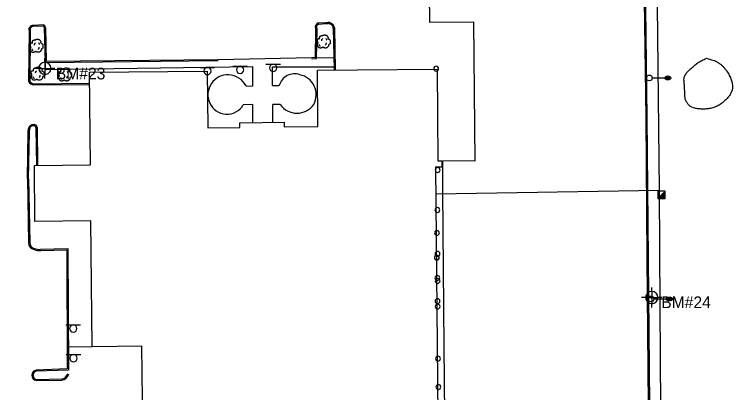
# Model space of a CAD drawing. Extents: x 2145380 to 2156929, y 139568 to 149130.
# Drawn here: x 2149393.4 to 2149761.7, y 142594.4 to 142788.2 of the extents above; entities that cross this region are included whole.
import ezdxf

# ---------------------------------------------------------------- set-up
doc = ezdxf.new("R2010")
doc.units = 0
for name, color, linetype in [('SURV_Benchmark', 7, 'Continuous'), ('SURV_Text', 7, 'Continuous'), ('TOPO_Asphalt', 7, 'Continuous'), ('TOPO_Building', 7, 'Continuous'), ('TOPO_Curb Back', 7, 'Continuous'), ('TOPO_Fence', 7, 'Continuous'), ('TOPO_Guardrail', 7, 'Continuous'), ('TOPO_Light Pole', 7, 'Continuous'), ('TOPO_Misc', 7, 'Continuous'), ('TOPO_Sidewalk', 7, 'Continuous'), ('TOPO_Sign', 7, 'Continuous'), ('TOPO_Tree', 7, 'Continuous'), ('TOPO_Tree Line', 7, 'Continuous')]:
    doc.layers.add(name, color=color, linetype=linetype)

# ---------------------------------------------------------------- blocks, each defined once
blk = doc.blocks.new('POST')
at = {"layer": 'TOPO_Misc'}
for start, end in [(89.99996, 180.00004), (179.99996, 270.00004), (359.99996, 90.00004), (269.99996, 0.00004)]:
    blk.add_arc((-0.01, 0.03), 3.16, start, end, dxfattribs=at)
blk = doc.blocks.new('LP')
at = {"layer": 'TOPO_Light Pole'}
blk.add_line((3.81, 0), (20.32, 0), dxfattribs=at)
for points in [[(20.32, 0), (27.94, 0)], [(20.32, 0), (23.5, 0)], [(20.83, 1.27), (27.43, 1.27)], [(20.83, 1.27), (23.5, 1.27)], [(23.71, 1.27), (27.43, 1.27)], [(23.71, 0), (27.94, 0)], [(20.83, -1.27), (27.43, -1.27)], [(20.83, -1.27), (23.5, -1.27)], [(23.71, -1.27), (27.43, -1.27)]]:
    blk.add_lwpolyline(points, dxfattribs=at)
blk.add_circle((0, 0), 3.81, dxfattribs=at)
blk.add_ellipse((24.13, 0), major_axis=(3.81, 0), ratio=0.666667, dxfattribs=at)
blk = doc.blocks.new('TREE')
at = {"layer": 'TOPO_Tree'}
for points in [[(-3.5, 17.6), (-3.1, 18.3), (-2.6, 18.8), (-1.9, 19.2), (-1, 19.7), (-0.2, 20), (0.7, 20.2), (1.6, 20.5), (2.5, 20.8), (3.4, 20.8), (4.1, 20.7), (4.8, 20.5), (5.5, 20.2), (6.4, 19.9), (7.3, 19.7), (8.2, 19.2), (9.4, 18.4), (10, 17.2), (10.8, 16), (11.2, 15.3), (11.6, 14.6), (11.9, 13.9), (12.2, 13.1), (11.4, 12), (11.9, 11.2), (12, 11), (12.2, 10.9), (12.4, 10.7), (12.9, 10.4), (13.5, 10), (14, 9.7), (14.7, 9.2), (15.4, 8.7), (16.1, 8.1), (16.7, 7.5), (16.9, 6.7), (17.1, 6), (17.6, 4.4), (17.7, 2.8), (17.7, 1.2), (17.7, -0.2), (17.8, -2.2), (16.6, -3), (15.5, -3.8), (14.3, -4.6), (13.2, -5.3)], [(-14.1, -0.4), (-14.2, 0.5), (-14.4, 1.4), (-14.6, 2.3), (-14.8, 3.2), (-15.5, 4), (-15.7, 4.9), (-15.8, 5.6), (-15.7, 6.3), (-15.7, 7), (-15.6, 7.9), (-15.7, 8.8), (-15.1, 9.7), (-14.6, 10.4), (-13.8, 10.5), (-13, 10.7), (-12.2, 11), (-11.1, 10), (-10.4, 10.7), (-9.4, 11.7), (-10.3, 13.3), (-9.8, 14.4), (-9.6, 15.1), (-9.3, 15.9), (-8.8, 16.5), (-8.2, 17.3), (-7.5, 17.7), (-6.7, 18.1), (-6.1, 18.4), (-5.6, 18.6), (-5.1, 18.7), (-4.5, 18.7), (-4, 18.5), (-3.5, 18.1)], [(13.2, -5.3), (13.3, -5.8), (13.4, -6.3), (13.4, -6.7), (13.8, -8.5), (12.2, -10), (10.8, -11.5), (10, -12.3), (9.1, -12.8), (8.2, -13.1), (6, -13.8), (3.3, -13.6), (1.3, -13.1), (0.5, -12.9), (-0.1, -11.4), (-0.8, -11.5), (-2, -11.6), (-3.3, -12.8), (-4.5, -13.1), (-6.1, -13.5), (-7.8, -14), (-9.3, -13.6), (-11.4, -13.1), (-12.8, -11.4), (-14.1, -9.4), (-15.3, -7.3), (-15.6, -5.1), (-15.1, -3), (-14.9, -1.9), (-13.9, -0.8), (-13.5, 0.1)], [(-4.2, 5.1), (-4.5, 6.1), (-4.3, 7.2), (-3.8, 8.2), (-3.3, 9.3), (-2.7, 10.3), (-1.6, 11)], [(5.9, 11.2), (6.5, 10.7), (7, 10.2), (7.4, 9.5), (7.9, 8.6), (8.3, 7.6), (8.5, 6.6)], [(-11.4, -4.5), (-11.5, -5.4), (-11, -6.3), (-10.1, -7.2), (-9.3, -8), (-8.5, -8.3), (-7.7, -8.1)], [(4.8, -6.3), (5.7, -5.7), (6.3, -4.9), (6.8, -3.9), (7.4, -2.8), (7.6, -1.7), (7.5, -0.6)]]:
    blk.add_open_spline(points, degree=3, dxfattribs=at)
blk = doc.blocks.new('BM')
at = {"layer": 'SURV_Benchmark'}
for p, q in [((0, 2.49), (0, 4.15)), ((-2.49, 0), (-4.16, 0)), ((4.16, 0), (2.49, 0)), ((0, -4.16), (0, -2.49))]:
    blk.add_line(p, q, dxfattribs=at)
for points in [[(-2.5, 0), (-2.49, 0), (0, 0), (0, -2.49), (0, -2.49)], [(-2.5, 0), (-2.49, 0), (0, 0), (0, -2.49), (0, -2.49)], [(0, 2.49), (0, 2.49), (0, 0), (2.49, 0), (2.49, 0), (2.49, 0)], [(0, 2.49), (0, 2.49), (0, 0), (2.49, 0), (2.49, 0), (2.49, 0), (2.49, 0)]]:
    blk.add_lwpolyline(points, dxfattribs=at)
for start, end in [(90.0638, 180.0068), (0.0638, 90.0068), (0.0638, 90.0068), (180.0638, 270.0068), (180.0638, 270.0068), (269.9472, 359.9927)]:
    blk.add_arc((0, 0), 2.5, start, end, dxfattribs=at)

msp = doc.modelspace()

# ---------------------------------------------------------------- linework, layer by layer
at = {"layer": 'TOPO_Asphalt'}
for p, q in [((2149497.86, 142765.14), (2149545.93, 142766.12)), ((2149433.22, 142617.88), (2149421.13, 142617.74))]:
    msp.add_line(p, q, dxfattribs=at)
for points in [[(2149606.28, 142858.04), (2149605.34, 142855.59), (2149606.23, 142784.2), (2149628.79, 142784.4), (2149629.5, 142713.03), (2149613.04, 142713.21)], [(2149508.62, 142334.14), (2149508.22, 142374.35), (2149507.88, 142422.77), (2149507.62, 142449.78), (2149615.27, 142450.93), (2149614.82, 142512.32), (2149613.8, 142618.02), (2149613.11, 142697.76), (2149613.04, 142713.21)]]:
    msp.add_lwpolyline(points, dxfattribs=at)
at = {"layer": 'TOPO_Building'}
msp.add_lwpolyline([(2149609.37, 142709.97), (2149611.79, 142454.29), (2149510.61, 142453.33), (2149509.43, 142577.65), (2149459.22, 142577.18), (2149458.83, 142618.13), (2149433.22, 142617.88), (2149432.62, 142682.34), (2149403.97, 142682.07), (2149403.7, 142710.8), (2149432.4, 142711.07), (2149431.96, 142758.58), (2149492.26, 142759.15), (2149492.53, 142730.12), (2149508.97, 142730.27), (2149508.95, 142732.72), (2149531.78, 142732.94), (2149531.8, 142730.68), (2149549.04, 142730.84), (2149548.77, 142759.65), (2149610.15, 142760.23), (2149610.59, 142713.21), (2149612.5, 142713.23), (2149612.53, 142710)], close=True, dxfattribs=at)
at = {"layer": 'TOPO_Curb Back'}
for points in [[(2149724.47, 142959.81), (2149715.64, 142934.83), (2149716.04, 142899.09), (2149716.63, 142819.51), (2149717.72, 142735.34), (2149718.33, 142663.2), (2149719, 142588.2), (2149719.83, 142507.61), (2149720.53, 142432.08), (2149721.11, 142361.61), (2149708.5, 142361.77)], [(2149723.9, 142960.01), (2149715.04, 142934.93), (2149715.44, 142899.09), (2149716.03, 142819.5), (2149717.12, 142735.34), (2149717.73, 142663.2), (2149718.4, 142588.19), (2149719.23, 142507.61), (2149719.93, 142432.08), (2149720.51, 142362.22), (2149708.55, 142362.37)], [(2149408.27, 142782.8), (2149403, 142782.61)], [(2149408.29, 142782.2), (2149403.01, 142782.01)], [(2149408.24, 142782.8), (2149408.44, 142782.82)], [(2149408.31, 142782.2), (2149408.35, 142782.21)], [(2149545.93, 142766.12), (2149547.78, 142766.22), (2149547.98, 142780.35), (2149547.83, 142782.41)], [(2149545.96, 142765.52), (2149548.37, 142765.65), (2149548.58, 142780.36), (2149548.44, 142782.32)], [(2149549.5, 142783.83), (2149553.01, 142784.15), (2149554.35, 142784.13)], [(2149549.58, 142783.23), (2149553.03, 142783.55), (2149554.31, 142783.53)], [(2149400.91, 142779.91), (2149400.69, 142753.95)], [(2149401.51, 142779.98), (2149401.29, 142754.09)], [(2149408.68, 142781.47), (2149409.12, 142763.6), (2149497.85, 142764.53)], [(2149409.29, 142781.42), (2149409.71, 142764.21), (2149497.85, 142765.13)], [(2149556.88, 142781.24), (2149557.29, 142759.73)], [(2149557.48, 142781.3), (2149557.89, 142759.74)], [(2149403.42, 142752.64), (2149432.01, 142752.9)], [(2149403.39, 142752.04), (2149432.02, 142752.3)], [(2149400.08, 142703.97), (2149400.55, 142727.98), (2149400.67, 142729.64), (2149401.27, 142731.12), (2149402.38, 142731.79), (2149403.62, 142731.89), (2149404.62, 142731.44), (2149405.06, 142730.14), (2149405.35, 142710.84)], [(2149400.68, 142703.96), (2149401.15, 142727.96), (2149401.26, 142729.5), (2149401.76, 142730.71), (2149402.57, 142731.21), (2149403.51, 142731.28), (2149404.14, 142731), (2149404.46, 142730.03), (2149404.75, 142710.83)], [(2149400.08, 142703.95), (2149400.66, 142671.26)], [(2149400.68, 142703.97), (2149401.26, 142671.27)], [(2149406.88, 142667.82), (2149420.85, 142668.2), (2149421.12, 142605.92), (2149404.61, 142605.37)], [(2149406.91, 142667.22), (2149420.25, 142667.58), (2149420.51, 142606.5), (2149404.54, 142605.97)], [(2149404.54, 142600.56), (2149417.71, 142600.8)], [(2149404.6, 142601.16), (2149417.68, 142601.4)]]:
    msp.add_lwpolyline(points, dxfattribs=at)
for centre, radius, start, end in [((2149403.05, 142780.41), 2.2, 91.4144, 193.2446), ((2149403.05, 142780.41), 1.6, 91.3012, 195.6343), ((2149408.02, 142781.61), 0.678, 347.4065, 60.8771), ((2149408.02, 142781.61), 1.28, 351.2252, 70.8275), ((2149549.84, 142781.74), 2.11, 99.1587, 161.5469), ((2149549.84, 142781.74), 1.51, 99.8707, 157.408), ((2149553.83, 142779.78), 3.78, 50.3588, 82.6067), ((2149553.82, 142779.78), 4.38, 49.4355, 83.0536), ((2149553.38, 142780.54), 3.57, 11.1799, 36.9238), ((2149553.38, 142780.54), 4.17, 10.4248, 37.8907), ((2149403.77, 142755.43), 3.41, 205.627, 263.598), ((2149403.77, 142755.43), 2.82, 208.3368, 262.8912), ((2149404.29, 142671.26), 3.63, 179.9063, 258.5311), ((2149404.29, 142671.26), 3.03, 179.8021, 259.4834), ((2149406.28, 142674.67), 6.88, 248.254, 274.9741), ((2149406.28, 142674.67), 7.48, 248.6946, 274.8345), ((2149405.13, 142603.26), 2.77, 102.3525, 257.6932), ((2149405.13, 142603.26), 2.17, 103.7161, 255.9485), ((2149417.35, 142604.88), 3.49, 275.4565, 347.3252), ((2149417.35, 142604.88), 4.09, 275.1212, 347.3255)]:
    msp.add_arc(centre, radius, start, end, dxfattribs=at)
at = {"layer": 'TOPO_Fence'}
msp.add_lwpolyline([(2149609.5, 142696.32), (2149724.03, 142698.22), (2149724.39, 142638.28), (2149725.28, 142508.97), (2149727.29, 142327.5), (2149413.94, 142323.87), (2149328.96, 142323.33)], dxfattribs=at)
at = {"layer": 'TOPO_Guardrail'}
msp.add_lwpolyline([(2149605.08, 142940.65), (2149657.25, 142941.77), (2149721.28, 142942.17), (2149722.59, 142824.45), (2149724.03, 142698.22)], dxfattribs=at)
at = {"layer": 'TOPO_Misc'}
for p, q in [((2149723.4, 142693.93), (2149727.14, 142697.68)), ((2149726.73, 142697.27), (2149727.14, 142697.27)), ((2149726.92, 142697.46), (2149727.14, 142697.46)), ((2149727.1, 142697.64), (2149727.14, 142697.64)), ((2149723.55, 142694.09), (2149727.14, 142694.09)), ((2149723.75, 142694.28), (2149727.14, 142694.28)), ((2149723.93, 142694.46), (2149727.14, 142694.46)), ((2149724.12, 142694.65), (2149727.14, 142694.65)), ((2149724.3, 142694.84), (2149727.14, 142694.84)), ((2149724.49, 142695.03), (2149727.14, 142695.03)), ((2149724.68, 142695.22), (2149727.14, 142695.22)), ((2149724.86, 142695.4), (2149727.14, 142695.4)), ((2149725.05, 142695.59), (2149727.14, 142695.59)), ((2149725.24, 142695.77), (2149727.14, 142695.77)), ((2149725.42, 142695.96), (2149727.14, 142695.96)), ((2149725.61, 142696.15), (2149727.14, 142696.15)), ((2149725.8, 142696.33), (2149727.14, 142696.33)), ((2149725.99, 142696.52), (2149727.14, 142696.52)), ((2149726.17, 142696.7), (2149727.14, 142696.7)), ((2149726.36, 142696.89), (2149727.14, 142696.89)), ((2149726.55, 142697.08), (2149727.14, 142697.08))]:
    msp.add_line(p, q, dxfattribs=at)
msp.add_lwpolyline([(2149727.14, 142693.93), (2149727.14, 142697.68), (2149723.39, 142697.67), (2149723.4, 142693.93), (2149727.14, 142693.93)], dxfattribs=at)
at = {"layer": 'TOPO_Sidewalk'}
for p, q in [((2149548.38, 142765.93), (2149557.17, 142766.12)), ((2149515.48, 142742.01), (2149515.47, 142732.78)), ((2149526, 142732.88), (2149525.92, 142742.11))]:
    msp.add_line(p, q, dxfattribs=at)
for points in [[(2149409.12, 142763.57), (2149409.28, 142759.9), (2149515.51, 142761.57), (2149515.49, 142751.43)], [(2149525.84, 142751.79), (2149525.75, 142761.32), (2149557.55, 142761.41)], [(2149512.2, 142751.58), (2149515.49, 142751.43)], [(2149525.84, 142751.79), (2149529.16, 142751.77)], [(2149515.48, 142742.01), (2149510.76, 142741.84)], [(2149529.69, 142742.04), (2149525.92, 142742.11)]]:
    msp.add_lwpolyline(points, dxfattribs=at)
for centre, radius, start, end in [((2149502.8, 142747.07), 10.15, 86.8448, 204.9441), ((2149503.03, 142746.93), 10.27, 26.8725, 88.1815), ((2149537.08, 142749.52), 8.23, 70.8436, 164.132), ((2149537.74, 142747.07), 10.42, 331.5494, 78.6885), ((2149502.42, 142746.72), 9.66, 203.9717, 329.7052), ((2149538.27, 142748.07), 10.49, 215.0648, 325.3548)]:
    msp.add_arc(centre, radius, start, end, dxfattribs=at)
at = {"layer": 'TOPO_Sign'}
for points in [[(2149488.61, 142761.08), (2149496.1, 142761.09)], [(2149492.36, 142761.08), (2149492.36, 142761.08)], [(2149505.37, 142761.67), (2149512.86, 142761.68)], [(2149507.25, 142759.8), (2149507.25, 142759.8)], [(2149509.12, 142761.67), (2149509.12, 142761.67)], [(2149510.98, 142759.8), (2149510.98, 142759.8)], [(2149522.37, 142762.7), (2149529.86, 142762.7)], [(2149524.25, 142760.83), (2149524.25, 142760.83)], [(2149526.12, 142762.7), (2149526.12, 142762.7)], [(2149527.99, 142760.83), (2149527.99, 142760.83)], [(2149490.49, 142759.22), (2149490.49, 142759.22)], [(2149492.36, 142757.35), (2149492.36, 142757.35)], [(2149494.22, 142759.22), (2149494.22, 142759.22)], [(2149509.12, 142757.93), (2149509.12, 142757.93)], [(2149526.12, 142758.96), (2149526.12, 142758.96)], [(2149419.87, 142629.13), (2149427.36, 142629.13)], [(2149421.75, 142627.26), (2149421.75, 142627.26)], [(2149423.62, 142629.13), (2149423.62, 142629.13)], [(2149425.49, 142627.26), (2149425.49, 142627.26)], [(2149423.62, 142625.39), (2149423.62, 142625.39)], [(2149419.98, 142613.92), (2149427.48, 142613.93)], [(2149423.73, 142613.92), (2149423.73, 142613.92)], [(2149421.87, 142612.05), (2149421.87, 142612.05)], [(2149423.73, 142610.18), (2149423.73, 142610.18)], [(2149425.6, 142612.05), (2149425.6, 142612.05)]]:
    msp.add_lwpolyline(points, dxfattribs=at)
for centre, start, end in [((2149492.36, 142759.22), 90, 180), ((2149492.36, 142759.22), 360, 90), ((2149509.12, 142759.8), 90, 180), ((2149509.12, 142759.8), 180, 270), ((2149509.12, 142759.8), 360, 90), ((2149509.12, 142759.8), 270, 0), ((2149526.12, 142760.83), 90, 180), ((2149526.12, 142760.83), 180, 270), ((2149526.12, 142760.83), 360, 90), ((2149526.12, 142760.83), 270, 0), ((2149492.36, 142759.22), 180, 270), ((2149492.36, 142759.22), 270, 0), ((2149423.62, 142627.26), 90, 180), ((2149423.62, 142627.26), 180, 270), ((2149423.62, 142627.26), 360, 90), ((2149423.62, 142627.26), 270, 0), ((2149423.73, 142612.05), 90, 180), ((2149423.73, 142612.05), 360, 90), ((2149423.73, 142612.05), 180, 270), ((2149423.73, 142612.05), 270, 0)]:
    msp.add_arc(centre, 1.87, start, end, dxfattribs=at)
at = {"layer": 'TOPO_Tree Line'}
msp.add_open_spline([(2149748.27, 142765.8), (2149747.23, 142765.26), (2149746.18, 142764.72), (2149745.13, 142764.19), (2149744.2, 142763.71), (2149743.39, 142763.02), (2149742.56, 142762.37), (2149741.56, 142761.58), (2149740.62, 142760.75), (2149739.67, 142759.9), (2149738.98, 142759.28), (2149738.35, 142758.69), (2149737.81, 142757.86), (2149737.04, 142756.68), (2149736.7, 142755.4), (2149736.76, 142754.1), (2149736.81, 142753.05), (2149736.94, 142752), (2149737.01, 142750.95), (2149737.08, 142749.63), (2149737.1, 142748.31), (2149737.18, 142746.99), (2149737.26, 142745.51), (2149737.55, 142744.11), (2149738.47, 142742.76), (2149739.43, 142741.34), (2149740.8, 142740.59), (2149742.32, 142740.17), (2149743.22, 142739.92), (2149744.11, 142739.78), (2149745.02, 142739.74), (2149746.05, 142739.69), (2149747.08, 142739.66), (2149748.11, 142739.75), (2149749.25, 142739.84), (2149750.36, 142740.06), (2149751.48, 142740.38), (2149752.63, 142740.72), (2149753.7, 142741.16), (2149754.74, 142741.77), (2149755.7, 142742.33), (2149756.54, 142742.96), (2149757.36, 142743.69), (2149758.17, 142744.41), (2149758.87, 142745.16), (2149759.55, 142745.99), (2149760.13, 142746.72), (2149760.57, 142747.46), (2149760.98, 142748.33), (2149761.4, 142749.21), (2149761.67, 142750.12), (2149761.68, 142751.03), (2149761.68, 142751.86), (2149761.52, 142752.72), (2149761.27, 142753.55), (2149760.92, 142754.71), (2149760.54, 142755.81), (2149760, 142756.89), (2149759.38, 142758.14), (2149758.64, 142759.26), (2149757.76, 142760.35), (2149756.82, 142761.5), (2149755.82, 142762.51), (2149754.57, 142763.32), (2149753.83, 142763.8), (2149753.07, 142764.21), (2149752.25, 142764.48), (2149750.92, 142764.92), (2149749.6, 142765.36), (2149748.27, 142765.8)], degree=3, dxfattribs=at)

# ---------------------------------------------------------------- block references
at = {"layer": 'SURV_Benchmark', "xscale": 1.25, "yscale": 1.25}
for p in [(2149409.03, 142760.57), (2149720.2, 142643.12)]:
    msp.add_blockref('BM', p, dxfattribs=at)
at = {"layer": 'TOPO_Light Pole', "xscale": 0.39370000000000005, "yscale": 0.3937000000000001}
for p in [(2149718.94, 142755.65), (2149719.72, 142642.38)]:
    msp.add_blockref('LP', p, dxfattribs=at)
at = {"layer": 'TOPO_Misc', "xscale": 0.39370000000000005, "yscale": 0.3937000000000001}
for p in [(2149609.66, 142760.42), (2149610.44, 142708.43), (2149610.32, 142687.98), (2149610.06, 142676.2), (2149609.99, 142663.54), (2149610.34, 142665.51), (2149610.31, 142653.13), (2149610.4, 142651.6), (2149610.33, 142641.21), (2149610.41, 142638.46), (2149610.64, 142611.8), (2149610.82, 142597.23)]:
    msp.add_blockref('POST', p, dxfattribs=at)
at = {"layer": 'TOPO_Tree', "xscale": 0.19685000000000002, "yscale": 0.19685000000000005}
for p in [(2149404.59, 142771.48), (2149551.88, 142773.68), (2149405.16, 142757.2), (2149419.24, 142756.76)]:
    msp.add_blockref('TREE', p, dxfattribs=at)

# ---------------------------------------------------------------- texts
at = {"layer": 'SURV_Text'}
for s, p in [('BM#23', (2149414.64, 142754.89)), ('BM#24', (2149725.07, 142637.68))]:
    msp.add_text(s, height=6, dxfattribs=at).set_placement(p)

doc.saveas('drawing.dxf')
